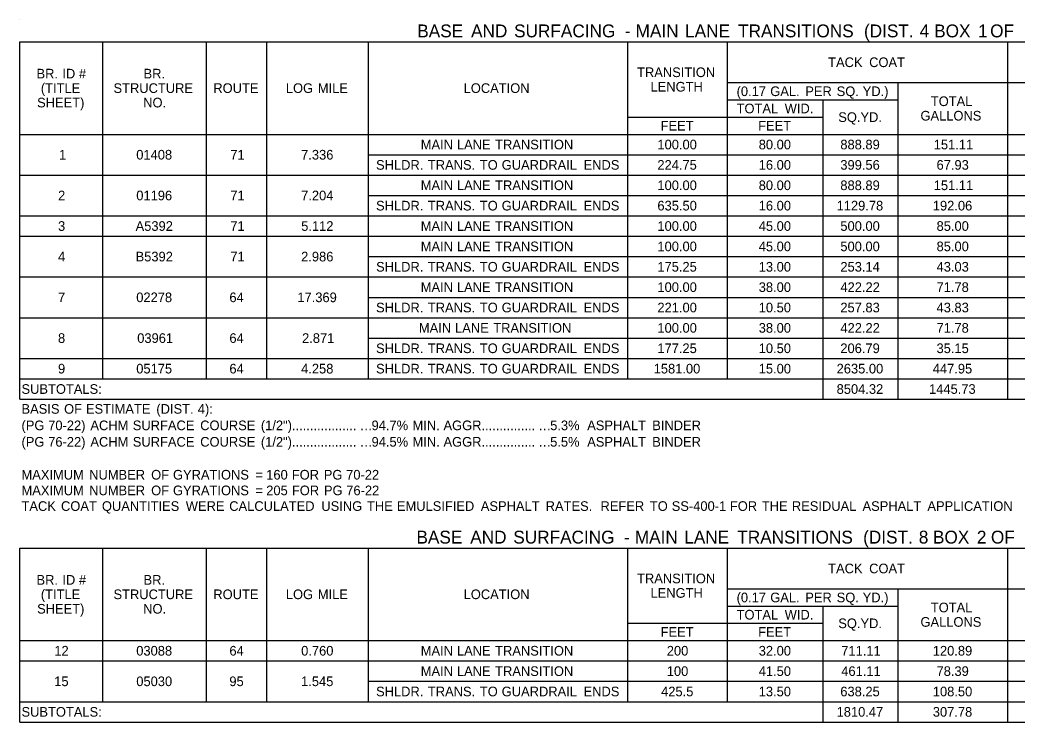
# Model space of a CAD drawing. Extents: x 540541 to 1930787, y -1948574 to 596640.
# Drawn here: x 554022 to 554642, y -1946532 to -1946096 of the extents above; entities that cross this region are included whole.
import ezdxf

# ---------------------------------------------------------------- set-up
doc = ezdxf.new("R2010")
doc.units = 0
doc.layers.add('Default', color=7, linetype='Continuous')
doc.layers.add('R_Border', color=7, linetype='Continuous')

msp = doc.modelspace()

# ---------------------------------------------------------------- linework, layer by layer
at = {"layer": 'Default'}
for p, q in [((554021.75, -1946109.32), (554900.22, -1946109.32)), ((554021.75, -1946331.62), (554021.75, -1946109.32)), ((554073.42, -1946166.84), (554073.42, -1946109.32)), ((554073.42, -1946318.94), (554073.42, -1946109.32)), ((554137.77, -1946318.94), (554137.77, -1946109.32)), ((554175.31, -1946318.94), (554175.31, -1946109.32)), ((554238.69, -1946318.94), (554238.69, -1946109.32)), ((554400.05, -1946318.94), (554400.05, -1946109.32)), ((554461.96, -1946318.94), (554461.96, -1946109.32)), ((554636.49, -1946331.62), (554636.49, -1946109.32)), ((554461.96, -1946134.67), (554900.22, -1946134.67)), ((554568.24, -1946145.39), (554568.24, -1946134.67)), ((554568.24, -1946331.62), (554568.24, -1946134.67)), ((554461.96, -1946145.39), (554568.24, -1946145.39)), ((554521.44, -1946331.62), (554521.44, -1946145.39)), ((554400.05, -1946156.12), (554461.96, -1946156.12)), ((554400.05, -1946156.12), (554521.44, -1946156.12)), ((554521.44, -1946166.84), (554521.44, -1946156.12)), ((554021.75, -1946166.84), (554900.22, -1946166.84)), ((554521.44, -1946166.84), (554900.22, -1946166.84)), ((554238.69, -1946179.52), (554900.22, -1946179.52)), ((554238.69, -1946179.52), (554900.22, -1946179.52)), ((554021.75, -1946192.19), (554900.22, -1946192.19)), ((554238.69, -1946192.19), (554900.22, -1946192.19)), ((554238.69, -1946204.87), (554900.22, -1946204.87)), ((554238.69, -1946204.87), (554900.22, -1946204.87)), ((554021.75, -1946217.54), (554900.22, -1946217.54)), ((554238.69, -1946217.54), (554900.22, -1946217.54)), ((554021.75, -1946230.22), (554900.22, -1946230.22)), ((554238.69, -1946230.22), (554900.22, -1946230.22)), ((554238.69, -1946242.89), (554900.22, -1946242.89)), ((554238.69, -1946242.89), (554900.22, -1946242.89)), ((554021.75, -1946255.57), (554900.22, -1946255.57)), ((554238.69, -1946255.57), (554900.22, -1946255.57)), ((554238.69, -1946268.24), (554900.22, -1946268.24)), ((554238.69, -1946268.24), (554900.22, -1946268.24)), ((554021.75, -1946280.92), (554900.22, -1946280.92)), ((554238.69, -1946280.92), (554900.22, -1946280.92)), ((554238.69, -1946293.59), (554900.22, -1946293.59)), ((554238.69, -1946293.59), (554900.22, -1946293.59)), ((554021.75, -1946306.27), (554900.22, -1946306.27)), ((554238.69, -1946306.27), (554900.22, -1946306.27)), ((554021.75, -1946318.94), (554900.22, -1946318.94)), ((554021.75, -1946318.94), (554900.22, -1946318.94)), ((554021.75, -1946331.62), (554900.22, -1946331.62)), ((554021.75, -1946424.24), (554900.22, -1946424.24)), ((554021.75, -1946532.47), (554021.75, -1946424.24)), ((554073.42, -1946519.79), (554073.42, -1946424.24)), ((554137.77, -1946519.79), (554137.77, -1946424.24)), ((554175.31, -1946519.79), (554175.31, -1946424.24)), ((554238.69, -1946519.79), (554238.69, -1946424.24)), ((554400.05, -1946519.79), (554400.05, -1946424.24)), ((554461.96, -1946519.79), (554461.96, -1946424.24)), ((554636.49, -1946532.47), (554636.49, -1946424.24)), ((554461.96, -1946449.59), (554900.22, -1946449.59)), ((554568.24, -1946460.32), (554568.24, -1946449.59)), ((554568.24, -1946532.47), (554568.24, -1946449.59)), ((554461.96, -1946460.32), (554568.24, -1946460.32)), ((554521.44, -1946532.47), (554521.44, -1946460.32)), ((554400.05, -1946471.04), (554461.96, -1946471.04)), ((554400.05, -1946471.04), (554521.44, -1946471.04)), ((554521.44, -1946481.77), (554521.44, -1946471.04)), ((554021.75, -1946481.77), (554900.22, -1946481.77)), ((554521.44, -1946481.77), (554900.22, -1946481.77)), ((554021.75, -1946494.44), (554175.31, -1946494.44)), ((554021.75, -1946494.44), (554137.77, -1946494.44)), ((554137.77, -1946494.44), (554900.22, -1946494.44)), ((554238.69, -1946494.44), (554820.27, -1946494.44)), ((554238.69, -1946507.12), (554820.27, -1946507.12)), ((554238.69, -1946507.12), (554780.3, -1946507.12)), ((554021.75, -1946519.79), (554900.22, -1946519.79)), ((554238.69, -1946519.79), (554400.05, -1946519.79)), ((554400.05, -1946519.79), (554900.22, -1946519.79)), ((554021.75, -1946532.47), (554900.22, -1946532.47))]:
    msp.add_line(p, q, dxfattribs=at)
at = {"layer": 'R_Border'}
msp.add_line((554021.75, -1946095.67), (554021.75, -1946095.67), dxfattribs=at)

# ---------------------------------------------------------------- texts
at = {"layer": 'Default'}
for s, height, p in [('BASE', 8, (554268.97, -1946106.49)), (' AND', 8, (554299.47, -1946106.49)), (' SURFACING', 8, (554326.24, -1946106.49)), (' MAIN', 8, (554401.86, -1946106.49)), (' LANE', 8, (554432.63, -1946106.49)), (' TRANSITIONS', 8, (554465.61, -1946106.49)), (' (DIST.', 8, (554543.94, -1946106.49)), (' 4', 8, (554578.56, -1946106.49)), (' BOX', 8, (554587.62, -1946106.49)), (' 1', 8, (554614.94, -1946106.49)), (' OF', 8, (554622.44, -1946106.49)), (' -', 8, (554395.12, -1946106.49)), ('TACK', 6, (554524.63, -1946124.99)), (' COAT', 6, (554547.91, -1946124.99)), ('BR.', 6, (554032.06, -1946132.08)), (' ID', 6, (554045.92, -1946132.08)), (' #', 6, (554056.22, -1946132.08)), ('BR.', 6, (554098.67, -1946132.08)), ('TRANSITION', 6, (554405.73, -1946131.22)), ('(TITLE', 6, (554034.76, -1946141.08)), ('STRUCTURE', 6, (554079.96, -1946141.08)), ('ROUTE', 6, (554142.08, -1946141.08)), ('LOG', 6, (554187.2, -1946141.08)), (' MILE', 6, (554204.86, -1946141.08)), ('LOCATION', 6, (554297.82, -1946141.08)), ('LENGTH', 6, (554414.09, -1946140.22)), ('(0.17', 6, (554467.66, -1946143.03)), (' GAL.', 6, (554486.38, -1946143.03)), (' PER', 6, (554508.16, -1946143.03)), (' SQ.', 6, (554527.69, -1946143.03)), (' YD.)', 6, (554543.88, -1946143.03)), ('SHEET)', 6, (554032.43, -1946150.08)), ('NO.', 6, (554098.44, -1946150.08)), ('TOTAL', 6, (554588.52, -1946149.25)), ('TOTAL', 6, (554467.67, -1946153.75)), (' WID.', 6, (554495.36, -1946153.75)), ('GALLONS', 6, (554582.07, -1946158.25)), ('FEET', 6, (554420.38, -1946164.48)), ('FEET', 6, (554481.07, -1946164.48)), ('SQ.YD.', 6, (554530.92, -1946159.12)), ('MAIN', 6, (554271.14, -1946176.18)), (' LANE', 6, (554291.41, -1946176.18)), (' TRANSITION', 6, (554315.19, -1946176.18)), ('100.00', 6, (554418.39, -1946176.18)), ('80.00', 6, (554481.42, -1946176.18)), ('888.89', 6, (554532.21, -1946176.18)), ('151.11', 6, (554590.32, -1946176.18)), ('1', 6, (554046.03, -1946182.52)), ('01408', 6, (554094.13, -1946182.52)), ('71', 6, (554152.65, -1946182.52)), ('7.336', 6, (554196.71, -1946182.52)), ('SHLDR.', 6, (554243.33, -1946188.85)), (' TRANS.', 6, (554273.34, -1946188.85)), (' TO', 6, (554305.68, -1946188.85)), (' GUARDRAIL', 6, (554319.28, -1946188.85)), (' ENDS', 6, (554370.22, -1946188.85)), ('224.75', 6, (554418.36, -1946188.85)), ('16.00', 6, (554481.42, -1946188.85)), ('399.56', 6, (554532.21, -1946188.85)), ('67.93', 6, (554592.07, -1946188.85)), ('MAIN', 6, (554271.14, -1946201.53)), (' LANE', 6, (554291.41, -1946201.53)), (' TRANSITION', 6, (554315.19, -1946201.53)), ('100.00', 6, (554418.39, -1946201.53)), ('80.00', 6, (554481.42, -1946201.53)), ('888.89', 6, (554532.21, -1946201.53)), ('151.11', 6, (554590.32, -1946201.53)), ('2', 6, (554045.48, -1946207.87)), ('01196', 6, (554094.14, -1946207.87)), ('71', 6, (554152.65, -1946207.87)), ('7.204', 6, (554196.72, -1946207.87)), ('SHLDR.', 6, (554243.33, -1946214.2)), (' TRANS.', 6, (554273.34, -1946214.2)), (' TO', 6, (554305.68, -1946214.2)), (' GUARDRAIL', 6, (554319.28, -1946214.2)), (' ENDS', 6, (554370.22, -1946214.2)), ('635.50', 6, (554418.39, -1946214.2)), ('16.00', 6, (554481.42, -1946214.2)), ('1129.78', 6, (554529.88, -1946214.2)), ('192.06', 6, (554589.74, -1946214.2)), ('3', 6, (554045.45, -1946226.88)), ('A5392', 6, (554093.71, -1946226.88)), ('71', 6, (554152.65, -1946226.88)), ('5.112', 6, (554196.74, -1946226.88)), ('MAIN', 6, (554271.14, -1946226.88)), (' LANE', 6, (554291.41, -1946226.88)), (' TRANSITION', 6, (554315.19, -1946226.88)), ('100.00', 6, (554418.39, -1946226.88)), ('45.00', 6, (554481.42, -1946226.88)), ('500.00', 6, (554532.22, -1946226.88)), ('85.00', 6, (554592.08, -1946226.88)), ('MAIN', 6, (554271.14, -1946239.55)), (' LANE', 6, (554291.41, -1946239.55)), (' TRANSITION', 6, (554315.19, -1946239.55)), ('100.00', 6, (554418.39, -1946239.55)), ('45.00', 6, (554481.42, -1946239.55)), ('500.00', 6, (554532.22, -1946239.55)), ('85.00', 6, (554592.08, -1946239.55)), ('4', 6, (554045.46, -1946245.89)), ('B5392', 6, (554093.71, -1946245.89)), ('71', 6, (554152.65, -1946245.89)), ('2.986', 6, (554196.71, -1946245.89)), ('SHLDR.', 6, (554243.33, -1946252.23)), (' TRANS.', 6, (554273.34, -1946252.23)), (' TO', 6, (554305.68, -1946252.23)), (' GUARDRAIL', 6, (554319.28, -1946252.23)), (' ENDS', 6, (554370.22, -1946252.23)), ('175.25', 6, (554418.36, -1946252.23)), ('13.00', 6, (554481.42, -1946252.23)), ('253.14', 6, (554532.23, -1946252.23)), ('43.03', 6, (554592.07, -1946252.23)), ('MAIN', 6, (554271.14, -1946264.9)), (' LANE', 6, (554291.41, -1946264.9)), (' TRANSITION', 6, (554315.19, -1946264.9)), ('100.00', 6, (554418.39, -1946264.9)), ('38.00', 6, (554481.42, -1946264.9)), ('422.22', 6, (554532.25, -1946264.9)), ('71.78', 6, (554592.06, -1946264.9)), ('7', 6, (554045.45, -1946271.24)), ('02278', 6, (554094.13, -1946271.24)), ('64', 6, (554152.09, -1946271.24)), ('17.369', 6, (554194.37, -1946271.24)), ('SHLDR.', 6, (554243.33, -1946277.58)), (' TRANS.', 6, (554273.34, -1946277.58)), (' TO', 6, (554305.68, -1946277.58)), (' GUARDRAIL', 6, (554319.28, -1946277.58)), (' ENDS', 6, (554370.22, -1946277.58)), ('221.00', 6, (554418.39, -1946277.58)), ('10.50', 6, (554481.42, -1946277.58)), ('257.83', 6, (554532.21, -1946277.58)), ('43.83', 6, (554592.07, -1946277.58)), ('MAIN', 6, (554269.97, -1946290.25)), (' LANE', 6, (554290.24, -1946290.25)), (' TRANSITION', 6, (554314.02, -1946290.25)), ('100.00', 6, (554418.39, -1946290.25)), ('38.00', 6, (554481.42, -1946290.25)), ('422.22', 6, (554532.25, -1946290.25)), ('71.78', 6, (554592.06, -1946290.25)), ('8', 6, (554045.44, -1946296.59)), ('03961', 6, (554094.72, -1946296.59)), ('64', 6, (554152.09, -1946296.59)), ('2.871', 6, (554197.29, -1946296.59)), ('SHLDR.', 6, (554243.33, -1946302.93)), (' TRANS.', 6, (554273.34, -1946302.93)), (' TO', 6, (554305.68, -1946302.93)), (' GUARDRAIL', 6, (554319.28, -1946302.93)), (' ENDS', 6, (554370.22, -1946302.93)), ('177.25', 6, (554418.36, -1946302.93)), ('10.50', 6, (554481.42, -1946302.93)), ('206.79', 6, (554532.21, -1946302.93)), ('35.15', 6, (554592.05, -1946302.93)), ('9', 6, (554045.44, -1946315.6)), ('05175', 6, (554094.12, -1946315.6)), ('64', 6, (554152.09, -1946315.6)), ('4.258', 6, (554196.7, -1946315.6)), ('SHLDR.', 6, (554243.33, -1946315.6)), (' TRANS.', 6, (554273.34, -1946315.6)), (' TO', 6, (554305.68, -1946315.6)), (' GUARDRAIL', 6, (554319.28, -1946315.6)), (' ENDS', 6, (554370.22, -1946315.6)), ('1581.00', 6, (554416.06, -1946315.6)), ('15.00', 6, (554481.42, -1946315.6)), ('2635.00', 6, (554529.89, -1946315.6)), ('447.95', 6, (554589.72, -1946315.6)), ('SUBTOTALS:', 6, (554022.72, -1946328.28)), ('8504.32', 6, (554529.9, -1946328.28)), ('1445.73', 6, (554587.4, -1946328.28)), ('BASIS', 6, (554022.72, -1946340.65)), (' OF', 6, (554046.99, -1946340.65)), (' ESTIMATE', 6, (554060.57, -1946340.65)), (' (DIST.', 6, (554104.38, -1946340.65)), (' 4):', 6, (554130.19, -1946340.65)), ('(PG', 6, (554022.72, -1946350.89)), (' 70-22)', 6, (554037.1, -1946350.89)), (' ACHM', 6, (554063.35, -1946350.89)), (' SURFACE', 6, (554089.73, -1946350.89)), (' COURSE', 6, (554131.68, -1946350.89)), (' (1/2")..................', 6, (554169.43, -1946350.89)), ('94.7%', 6, (554240.53, -1946350.89)), (' AGGR...............', 6, (554283.06, -1946350.89)), ('5.3%', 6, (554351.66, -1946350.89)), ('  ASPHALT', 6, (554370.24, -1946350.89)), ('…', 6, (554233.13, -1946350.89)), (' MIN.', 6, (554263.77, -1946350.89)), ('…', 6, (554344.26, -1946350.89)), (' BINDER', 6, (554412.94, -1946350.89)), ('(PG', 6, (554022.72, -1946361.13)), (' 76-22)', 6, (554037.1, -1946361.13)), (' ACHM', 6, (554063.35, -1946361.13)), (' SURFACE', 6, (554089.73, -1946361.13)), (' COURSE', 6, (554131.68, -1946361.13)), (' (1/2")..................', 6, (554169.43, -1946361.13)), ('94.5%', 6, (554240.53, -1946361.13)), (' MIN.', 6, (554263.77, -1946361.13)), (' AGGR...............', 6, (554283.06, -1946361.13)), ('5.5%', 6, (554351.66, -1946361.13)), ('  ASPHALT', 6, (554370.24, -1946361.13)), (' BINDER', 6, (554412.94, -1946361.13)), ('…', 6, (554233.13, -1946361.13)), ('…', 6, (554344.26, -1946361.13)), ('MAXIMUM', 6, (554022.72, -1946381.6)), (' NUMBER', 6, (554062.61, -1946381.6)), (' OF', 6, (554101.16, -1946381.6)), (' GYRATIONS', 6, (554114.75, -1946381.6)), (' 160', 6, (554172.77, -1946381.6)), (' FOR', 6, (554188.68, -1946381.6)), (' PG', 6, (554208.59, -1946381.6)), (' 70-22', 6, (554222.5, -1946381.6)), (' =', 6, (554166.02, -1946381.6)), ('MAXIMUM', 6, (554022.72, -1946391.35)), (' NUMBER', 6, (554062.61, -1946391.35)), (' OF', 6, (554101.16, -1946391.35)), (' GYRATIONS', 6, (554114.75, -1946391.35)), (' =', 6, (554166.02, -1946391.35)), (' 205', 6, (554172.77, -1946391.35)), (' FOR', 6, (554188.74, -1946391.35)), (' PG', 6, (554208.66, -1946391.35)), (' 76-22', 6, (554222.57, -1946391.35)), ('TACK', 6, (554022.72, -1946401.1)), (' COAT', 6, (554045.07, -1946401.1)), (' QUANTITIES', 6, (554070.52, -1946401.1)), (' WERE', 6, (554122.72, -1946401.1)), (' CALCULATED', 6, (554149.75, -1946401.1)), (' USING', 6, (554207.07, -1946401.1)), (' THE', 6, (554235.42, -1946401.1)), (' EMULSIFIED', 6, (554254.07, -1946401.1)), (' ASPHALT', 6, (554306.26, -1946401.1)), (' RATES.', 6, (554346.63, -1946401.1)), ('  REFER', 6, (554378.51, -1946401.1)), (' TO', 6, (554411.47, -1946401.1)), (' SS-400-1', 6, (554425.06, -1946401.1)), (' FOR', 6, (554461.26, -1946401.1)), (' THE', 6, (554481.17, -1946401.1)), (' RESIDUAL', 6, (554499.82, -1946401.1)), (' ASPHALT', 6, (554543.78, -1946401.1)), (' APPLICATION', 6, (554584.15, -1946401.1)), (' (DIST.', 8, (554543.43, -1946421.42)), ('BASE', 8, (554268.46, -1946421.42)), (' AND', 8, (554298.97, -1946421.42)), (' SURFACING', 8, (554325.74, -1946421.42)), (' -', 8, (554394.62, -1946421.42)), (' MAIN', 8, (554401.36, -1946421.42)), (' LANE', 8, (554432.13, -1946421.42)), (' TRANSITIONS', 8, (554465.11, -1946421.42)), (' 8', 8, (554578.05, -1946421.42)), (' BOX', 8, (554586.87, -1946421.42)), (' 2', 8, (554614.19, -1946421.42)), (' OF', 8, (554622.94, -1946421.42)), ('TACK', 6, (554524.63, -1946439.92)), (' COAT', 6, (554547.91, -1946439.92)), ('BR.', 6, (554032.06, -1946447)), (' ID', 6, (554045.92, -1946447)), (' #', 6, (554056.22, -1946447)), ('BR.', 6, (554098.67, -1946447)), ('TRANSITION', 6, (554405.73, -1946446.14)), ('(TITLE', 6, (554034.76, -1946456)), ('STRUCTURE', 6, (554079.96, -1946456)), ('ROUTE', 6, (554142.08, -1946456)), ('LOG', 6, (554187.2, -1946456)), (' MILE', 6, (554204.86, -1946456)), ('LOCATION', 6, (554297.82, -1946456)), ('LENGTH', 6, (554414.09, -1946455.14)), ('(0.17', 6, (554467.66, -1946457.95)), (' GAL.', 6, (554486.38, -1946457.95)), (' PER', 6, (554508.16, -1946457.95)), (' SQ.', 6, (554527.69, -1946457.95)), (' YD.)', 6, (554543.88, -1946457.95)), ('SHEET)', 6, (554032.43, -1946465)), ('NO.', 6, (554098.44, -1946465)), ('TOTAL', 6, (554467.67, -1946468.68)), (' WID.', 6, (554495.36, -1946468.68)), ('TOTAL', 6, (554588.52, -1946464.18)), ('SQ.YD.', 6, (554530.92, -1946474.04)), ('GALLONS', 6, (554582.07, -1946473.18)), ('FEET', 6, (554420.38, -1946479.4)), ('FEET', 6, (554481.07, -1946479.4)), ('12', 6, (554043.15, -1946491.1)), ('03088', 6, (554094.13, -1946491.1)), ('64', 6, (554152.09, -1946491.1)), ('0.760', 6, (554196.72, -1946491.1)), ('MAIN', 6, (554271.14, -1946491.1)), (' LANE', 6, (554291.41, -1946491.1)), (' TRANSITION', 6, (554315.19, -1946491.1)), ('200', 6, (554424.22, -1946491.1)), ('32.00', 6, (554481.42, -1946491.1)), ('711.11', 6, (554532.79, -1946491.1)), ('120.89', 6, (554589.73, -1946491.1)), ('MAIN', 6, (554271.14, -1946503.78)), (' LANE', 6, (554291.41, -1946503.78)), (' TRANSITION', 6, (554315.19, -1946503.78)), ('100', 6, (554424.22, -1946503.78)), ('41.50', 6, (554481.42, -1946503.78)), ('461.11', 6, (554532.79, -1946503.78)), ('78.39', 6, (554592.06, -1946503.78)), ('15', 6, (554043.09, -1946510.12)), ('05030', 6, (554094.15, -1946510.12)), ('95', 6, (554152.05, -1946510.12)), ('1.545', 6, (554196.68, -1946510.12)), ('SHLDR.', 6, (554243.33, -1946516.45)), (' TRANS.', 6, (554273.34, -1946516.45)), (' TO', 6, (554305.68, -1946516.45)), (' GUARDRAIL', 6, (554319.28, -1946516.45)), (' ENDS', 6, (554370.22, -1946516.45)), ('425.5', 6, (554420.69, -1946516.45)), ('13.50', 6, (554481.42, -1946516.45)), ('638.25', 6, (554532.19, -1946516.45)), ('108.50', 6, (554589.75, -1946516.45)), ('SUBTOTALS:', 6, (554022.72, -1946529.13)), ('1810.47', 6, (554529.88, -1946529.13)), ('307.78', 6, (554589.74, -1946529.13))]:
    msp.add_text(s, height=height, dxfattribs=at).set_placement(p)

doc.saveas('drawing.dxf')
